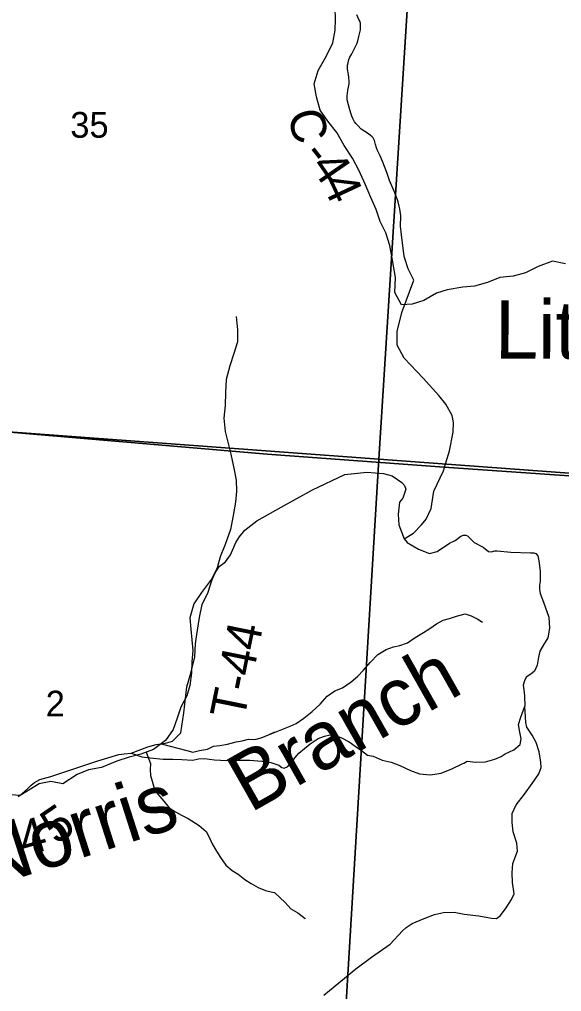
# Model space of a CAD drawing. Extents: x 0 to 34, y 0 to 22.
# Drawn here: x 5.252 to 6.132, y 18.512 to 20.093 of the extents above; entities that cross this region are included whole.
import ezdxf

# ---------------------------------------------------------------- set-up
doc = ezdxf.new("R2010")
doc.units = 0
for name, color, linetype in [('GM_X_Corporation', 7, 'Continuous'), ('GM_X_County_Road', 7, 'Continuous'), ('GM_X_County_Road_Text', 7, 'Continuous'), ('GM_X_Minor_River', 7, 'Continuous'), ('GM_X_Minor_River_Text', 7, 'Continuous'), ('GM_X_Section_Text', 7, 'Continuous'), ('GM_X_Township_Road', 7, 'Continuous'), ('GM_X_Township_Road_Text', 7, 'Continuous')]:
    doc.layers.add(name, color=color, linetype=linetype)

msp = doc.modelspace()

# ---------------------------------------------------------------- linework, layer by layer
at = {"layer": 'GM_X_Corporation'}
for points in [[(6.9348, 20.9), (2.1, 20.9), (2.1, 19.6396), (2.105, 19.6393), (2.5886, 19.6074), (3.0215, 19.5789), (3.8201, 19.5262), (3.8692, 19.5228), (4.8375, 19.4557), (5.0201, 19.4401), (5.6539, 19.3859), (5.9419, 19.3649), (6.5423, 19.3229), (6.824, 19.3005), (6.835, 19.4037), (6.8961, 20.3303), (6.9032, 20.4198)], [(4.8871, 20.4794), (5.901, 20.4176), (5.8355, 19.3781), (4.8445, 19.4512)], [(6.9011, 20.3385), (6.8376, 19.4096), (6.8303, 19.3047), (5.8355, 19.3781), (5.901, 20.4176)], [(4.8445, 19.4512), (5.8355, 19.3781), (5.775, 18.3681), (4.7598, 18.4308)], [(5.8355, 19.3781), (6.8303, 19.3047), (6.7676, 18.3985), (6.7615, 18.3053), (5.775, 18.3681)]]:
    msp.add_lwpolyline(points, close=True, dxfattribs=at)
msp.add_lwpolyline([(6.7043, 17.4985), (6.7536, 18.2991), (6.7629, 18.3924), (6.7876, 18.7583), (6.824, 19.3005), (6.5423, 19.3229), (5.9419, 19.3649), (5.6539, 19.3859), (5.0201, 19.4401), (4.8375, 19.4557), (3.8692, 19.5228), (3.8201, 19.5262), (3.0215, 19.5789), (2.5886, 19.6074), (2.105, 19.6393), (2.1, 19.6396), (2.1, 16.1353)], dxfattribs=at)
at = {"layer": 'GM_X_County_Road'}
for points in [[(5.8698, 19.7849), (5.8688, 19.7894), (5.8668, 19.7965), (5.8659, 19.7997), (5.8634, 19.8067), (5.8618, 19.8111), (5.8584, 19.8189), (5.8531, 19.8311), (5.8486, 19.8442), (5.842, 19.8611), (5.8378, 19.8711), (5.8368, 19.8733), (5.8355, 19.8754), (5.8335, 19.8799), (5.8318, 19.8841), (5.8304, 19.8895), (5.8284, 19.8961), (5.8272, 19.8984), (5.8263, 19.9005), (5.8249, 19.9021), (5.8221, 19.9042), (5.8186, 19.9072), (5.8129, 19.911), (5.807, 19.9148), (5.8013, 19.9205), (5.7981, 19.9236), (5.7958, 19.9267), (5.7936, 19.9309), (5.7916, 19.9357), (5.7901, 19.9406), (5.7877, 19.948), (5.7861, 19.9541), (5.7843, 19.9626), (5.7843, 19.9686), (5.7852, 19.9774), (5.7873, 19.9885), (5.7871, 19.9921), (5.787, 19.9988), (5.7863, 20.0033), (5.7848, 20.0124), (5.7848, 20.0187), (5.7856, 20.0226), (5.787, 20.0279), (5.7885, 20.032), (5.7916, 20.0374), (5.8004, 20.0543), (5.8015, 20.0584), (5.8028, 20.0651), (5.8056, 20.0761), (5.8057, 20.0868), (5.8053, 20.0889), (5.8048, 20.0905), (5.8033, 20.093), (5.7996, 20.1007)], [(5.9427, 19.3663), (5.9504, 19.3912), (5.9562, 19.4218), (5.9568, 19.4375), (5.9545, 19.449), (5.9445, 19.4675), (5.9329, 19.4813), (5.9076, 19.5097), (5.8769, 19.542), (5.8653, 19.5635), (5.8653, 19.5858), (5.873, 19.6166), (5.8922, 19.6692), (5.8834, 19.6876), (5.8773, 19.7057), (5.876, 19.7119), (5.8723, 19.743), (5.871, 19.7568), (5.8713, 19.7736), (5.8698, 19.7849)], [(5.8768, 19.2482), (5.8917, 19.2573), (5.9049, 19.2713), (5.9124, 19.2804), (5.9206, 19.2978), (5.9248, 19.3259), (5.9405, 19.359), (5.9422, 19.3644), (5.9427, 19.3663)], [(5.9738, 18.8837), (5.9793, 18.8865), (5.9934, 18.8852), (6.0088, 18.8856), (6.0242, 18.8901), (6.0342, 18.8945), (6.0406, 18.8984), (6.0547, 18.9051), (6.0653, 18.9138), (6.0669, 18.9228), (6.0647, 18.934), (6.0624, 18.9465), (6.0663, 18.9584), (6.073, 18.9761)], [(5.9981, 18.6352), (6.0189, 18.6314), (6.0269, 18.6306), (6.0335, 18.6357), (6.0426, 18.648), (6.0513, 18.6617), (6.0555, 18.6707), (6.0527, 18.6893), (6.052, 18.7052), (6.0534, 18.7204), (6.061, 18.7405), (6.0596, 18.7536), (6.0541, 18.7716), (6.052, 18.7868), (6.052, 18.8014), (6.0589, 18.8159), (6.0721, 18.8332), (6.0845, 18.8505), (6.0956, 18.866), (6.0994, 18.8762), (6.0986, 18.8849), (6.0961, 18.902), (6.0911, 18.9173), (6.0845, 18.9289), (6.0758, 18.9418), (6.0745, 18.9497), (6.073, 18.9761)], [(5.2497, 18.8294), (5.2548, 18.833), (5.2651, 18.842), (5.2706, 18.8475), (5.2762, 18.8518), (5.2848, 18.8567), (5.3024, 18.862), (5.3788, 18.8872), (5.4128, 18.8977), (5.4216, 18.8987), (5.4333, 18.8997), (5.4502, 18.894), (5.4641, 18.8919), (5.4849, 18.8902), (5.5008, 18.8902), (5.5155, 18.8892), (5.5331, 18.8885), (5.5423, 18.8906), (5.5525, 18.8909), (5.5685, 18.8889), (5.5879, 18.8879), (5.6039, 18.8882), (5.626, 18.8882), (5.6457, 18.8865), (5.6603, 18.8848), (5.6729, 18.88), (5.6777, 18.8763), (5.6817, 18.8753), (5.6875, 18.878), (5.6943, 18.8861), (5.7055, 18.8998), (5.7239, 18.9151), (5.7368, 18.9236), (5.747, 18.9274), (5.7563, 18.9295), (5.7649, 18.9287), (5.774, 18.9251), (5.7871, 18.9183), (5.7973, 18.9113), (5.8075, 18.9039), (5.8173, 18.8962), (5.8263, 18.8949), (5.8407, 18.8885), (5.8555, 18.8849), (5.8696, 18.8798), (5.8872, 18.8714), (5.9014, 18.866), (5.9193, 18.8644), (5.9366, 18.8673), (5.9543, 18.8743), (5.971, 18.8824), (5.9738, 18.8837)], [(5.7461, 18.5063), (5.7644, 18.5215), (5.7984, 18.549), (5.8237, 18.5677), (5.8541, 18.5888), (5.8741, 18.6105), (5.88, 18.6163), (5.8896, 18.6225), (5.9092, 18.631), (5.9261, 18.6371), (5.9407, 18.6405), (5.9582, 18.6411), (5.9741, 18.6381), (5.9981, 18.6352)]]:
    msp.add_lwpolyline(points, dxfattribs=at)
at = {"layer": 'GM_X_Minor_River'}
for points in [[(6.1389, 19.6958), (6.1177, 19.6997), (6.0942, 19.6914), (6.0737, 19.6808), (6.054, 19.6756), (6.0321, 19.6734), (6.0124, 19.6651), (5.9912, 19.6591), (5.9722, 19.6576), (5.9465, 19.6532), (5.9291, 19.6479), (5.9086, 19.6358), (5.8896, 19.6298), (5.8722, 19.6291), (5.8617, 19.6489), (5.8625, 19.6731), (5.8573, 19.705), (5.8536, 19.7255), (5.8469, 19.746), (5.8378, 19.7642), (5.8311, 19.784), (5.8228, 19.8037), (5.8138, 19.8242), (5.8033, 19.8477), (5.7927, 19.8675), (5.7792, 19.888), (5.7671, 19.9093), (5.7528, 19.9275), (5.74, 19.9458), (5.734, 19.967), (5.7303, 19.9883), (5.7372, 20.0102), (5.7501, 20.033), (5.7608, 20.0549), (5.7646, 20.0754), (5.7654, 20.0928), (5.7647, 20.1126)], [(5.6035, 19.6097), (5.6061, 19.588), (5.606, 19.5686), (5.5999, 19.55), (5.5935, 19.5295), (5.5877, 19.5074), (5.5865, 19.4865), (5.5857, 19.4652), (5.5838, 19.4447), (5.5856, 19.423), (5.5909, 19.4032), (5.595, 19.3861), (5.6003, 19.3606), (5.6036, 19.3435), (5.604, 19.3256), (5.6028, 19.3077), (5.5986, 19.2861), (5.5947, 19.2636), (5.5856, 19.2393), (5.5776, 19.2188), (5.5726, 19.2009), (5.5635, 19.1827), (5.5472, 19.161), (5.535, 19.1427), (5.5285, 19.1199), (5.53, 19.1013), (5.5319, 19.0842), (5.5333, 19.0667), (5.5318, 19.048), (5.531, 19.0302), (5.5283, 19.01), (5.5237, 18.9929), (5.5138, 18.9743), (5.5077, 18.9564), (5.5016, 18.9381), (5.4891, 18.9203), (5.4694, 18.9058), (5.4489, 18.8982), (5.4296, 18.8933), (5.4099, 18.8869), (5.3849, 18.8766), (5.364, 18.8728), (5.3455, 18.8649), (5.322, 18.8497), (5.3023, 18.8539), (5.2834, 18.8501), (5.2527, 18.8311), (5.2292, 18.8323)], [(5.656, 18.9295), (5.6916, 18.9436), (5.7014, 18.9478), (5.7139, 18.9565), (5.7272, 18.9675), (5.7404, 18.9792), (5.7514, 18.9925), (5.7639, 19.0012), (5.7764, 19.0061), (5.7904, 19.0156), (5.8014, 19.0251), (5.8108, 19.0345), (5.8214, 19.047), (5.8339, 19.0603), (5.8472, 19.0683), (5.8593, 19.0724), (5.8695, 19.0747), (5.882, 19.0792), (5.8945, 19.0876), (5.9081, 19.0959), (5.9183, 19.1027), (5.9293, 19.1099), (5.9403, 19.116), (5.9505, 19.1187), (5.9615, 19.1224), (5.9759, 19.1262), (5.9857, 19.1232), (5.9963, 19.1175), (6.0039, 19.1126)], [(5.4819, 18.915), (5.5237, 18.9038), (5.5335, 18.9015), (5.5441, 18.9038), (5.557, 18.9064), (5.5668, 18.9109), (5.5771, 18.912), (5.5899, 18.9142), (5.6036, 18.918), (5.6134, 18.9198), (5.6236, 18.9225), (5.6339, 18.9217), (5.6445, 18.9246), (5.6562, 18.9295), (5.6664, 18.9344)], [(5.4577, 18.9015), (5.4646, 18.8828), (5.4638, 18.8733), (5.4645, 18.8635), (5.4672, 18.854), (5.4705, 18.843), (5.4766, 18.8331), (5.4864, 18.8216), (5.4951, 18.8106), (5.5053, 18.8041), (5.5151, 18.7988), (5.5257, 18.7934), (5.5434, 18.782), (5.5551, 18.7724), (5.5604, 18.7622), (5.5645, 18.7523), (5.5717, 18.7401), (5.5781, 18.7299), (5.5868, 18.7177), (5.597, 18.7089), (5.6068, 18.7028), (5.6178, 18.694), (5.628, 18.6879), (5.6397, 18.6811), (5.6514, 18.6765), (5.6627, 18.6738), (5.6658, 18.673)], [(5.6658, 18.673), (5.6832, 18.6567), (5.6926, 18.6464), (5.704, 18.64), (5.7161, 18.6309), (5.7165, 18.6316)]]:
    msp.add_lwpolyline(points, dxfattribs=at)
at = {"layer": 'GM_X_Township_Road'}
for points in [[(5.6768, 19.2996), (5.728, 19.328), (5.7802, 19.3532), (5.8162, 19.3568), (5.843, 19.3548), (5.8573, 19.351), (5.8727, 19.3399), (5.8775, 19.3352), (5.8793, 19.3292), (5.8744, 19.3143), (5.8694, 19.3077), (5.8669, 19.2887), (5.8678, 19.2713), (5.8768, 19.2482), (5.8815, 19.2421), (5.8999, 19.2317), (5.9178, 19.2247), (5.9305, 19.2276), (5.9506, 19.2415), (5.9594, 19.2454), (5.9686, 19.2524), (5.9732, 19.2542), (5.9769, 19.2543), (5.9795, 19.253), (5.9905, 19.2426), (6.005, 19.235), (6.0139, 19.2277), (6.0181, 19.227), (6.0238, 19.2286), (6.028, 19.2288), (6.0499, 19.2265), (6.0818, 19.2254), (6.0874, 19.2253), (6.0905, 19.2242), (6.0937, 19.2207), (6.0956, 19.2127), (6.0977, 19.1957), (6.0977, 19.1794), (6.0966, 19.1731), (6.0964, 19.1663), (6.0977, 19.1595), (6.1029, 19.1451), (6.1116, 19.1209), (6.1127, 19.103), (6.1104, 19.0874), (6.1029, 19.0759), (6.0972, 19.0655), (6.0949, 19.0557), (6.0926, 19.043), (6.0885, 19.0332), (6.0827, 19.028), (6.0752, 19.0234), (6.0724, 19.0176), (6.0701, 19.0101), (6.0712, 19.0026), (6.0724, 18.9928), (6.073, 18.9761)], [(5.4333, 18.8997), (5.4602, 18.9102), (5.4739, 18.9136), (5.4888, 18.9161), (5.5005, 18.9195), (5.5136, 18.9326), (5.5185, 18.9653), (5.5238, 19.0074), (5.53, 19.03), (5.5366, 19.0565), (5.5376, 19.0776), (5.5398, 19.0929), (5.5443, 19.1203), (5.5487, 19.1417), (5.558, 19.1618), (5.5644, 19.1803), (5.5691, 19.1921), (5.5759, 19.2033), (5.5862, 19.2109), (5.5943, 19.2224), (5.603, 19.2422), (5.6087, 19.2512), (5.6176, 19.2623), (5.6372, 19.2775), (5.6768, 19.2996)]]:
    msp.add_lwpolyline(points, dxfattribs=at)

# ---------------------------------------------------------------- texts
at = {"layer": 'GM_X_County_Road_Text'}
for s, rotation, p in [('C', 284.4291, (5.6866, 19.94)), ('-', 307.9436, (5.7093, 19.8721)), ('4', 304.5806, (5.7232, 19.8544)), ('4', 295.0859, (5.7418, 19.8278)), ('5', 34.3634, (5.3112, 18.7497)), ('4', 16.2034, (5.2599, 18.7315))]:
    msp.add_text(s, height=0.0568, rotation=rotation, dxfattribs=at).set_placement(p)
at = {"layer": 'GM_X_Minor_River_Text'}
for s, height, rotation, p in [('Little', 0.09469, 359.7569, (6.0239, 19.5415)), ('Branch', 0.0947, 29.4973, (5.6264, 18.8018)), ('Norris', 0.0947, 17.7682, (5.1944, 18.6783))]:
    msp.add_text(s, height=height, rotation=rotation, dxfattribs=at).set_placement(p)
at = {"layer": 'GM_X_Section_Text'}
for s, height, p in [('35', 0.04186, (5.3342, 19.9007)), ('2', 0.0419, (5.2942, 18.9594))]:
    msp.add_text(s, height=height, rotation=0, dxfattribs=at).set_placement(p)
at = {"layer": 'GM_X_Township_Road_Text'}
msp.add_text('T-44', height=0.05682, rotation=78.5052, dxfattribs=at).set_placement((5.6164, 18.9524))

doc.saveas('drawing.dxf')
